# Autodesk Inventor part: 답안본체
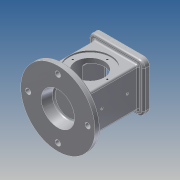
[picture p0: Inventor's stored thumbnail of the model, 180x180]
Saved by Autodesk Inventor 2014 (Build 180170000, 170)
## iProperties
Created: 2018-10
Part Number: 답안본체
Material: 알루미늄 6061
Document SubType Name: Modeling
Designer: net
Density: 2.71 g/cm^3
Appearance: 알루미늄 - 평지
Mass: 988.219 g
Surface Area: 743.902 cm^2
Volume: 364.656 cm^3
Author: net
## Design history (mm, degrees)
sketch "스케치1"
  geometry: C1 r 62.5 at (0, 0); 1 further point
  constraints: 1 centre point, 1 coincident
  dimensions: "d0" = 125 diameter of C1
extrude "돌출1" new body sketch "스케치1" distance "d1" = 10; taper "d2" = 0 deg
sketch "스케치2"
  geometry: L1 (-37, -33)-(37, -33); L2 (37, -33)-(37, 33); L3 (37, 33)-(-37, 33); L4 (-37, 33)-(-37, -33); L5 (-37, -33)-(37, 33); L6 (37, -33)-(-37, 33); C1 r 62.5 at (0, 0) reference
  constraints: 12 end point, 2 midpoint, 2 parallel, 1 horizontal, 1 perpendicular
  dimensions: "d3" = 66 distance of L3.end L1.start; "d4" = 74 distance of L2.end L3.end
extrude "돌출2" join sketch "스케치2" distance "d5" = 98; taper "d6" = 0 deg
sketch "스케치3"
  geometry: L1 (-37, -33)-(37, -33) reference; L2 (37, -33)-(37, 33) reference; L3 (37, 33)-(-37, 33) reference; L4 (-37, 33)-(-37, -33) reference; L5 (-46, -41)-(46, -41); L6 (46, -41)-(46, 41); L7 (46, 41)-(-46, 41); L8 (-46, 41)-(-46, -41); L9 (-46, -41)-(46, 41); L10 (46, -41)-(-46, 41); 1 further point
  constraints: 12 end point, 2 midpoint, 2 parallel, 1 horizontal, 1 perpendicular
  dimensions: "d7" = 92 distance of L6.end L7.end; "d8" = 82 distance of L7.end L5.start
extrude "돌출3" join sketch "스케치3" distance "d9" = 10; taper "d10" = 0 deg
sketch "스케치5"
  geometry: L1 (-26, -26)-(26, -26); L2 (26, -26)-(26, 26); L3 (26, 26)-(-26, 26); L4 (-26, 26)-(-26, -26); L5 (-26, -26)-(26, 26); L6 (26, -26)-(-26, 26); L7 (-22, -22)-(22, -22); L8 (22, -22)-(22, 22); L9 (22, 22)-(-22, 22); L10 (-22, 22)-(-22, -22); L11 (-22, -22)-(22, 22); L12 (22, -22)-(-22, 22); 1 further point
  constraints: 24 end point, 4 midpoint, 4 parallel, 2 horizontal, 2 perpendicular
  dimensions: "d16" = 52 distance of L2.end L3.end; "d17" = 52 distance of L3.end L1.start; "d18" = 44 distance of L8.end L9.end; "d19" = 44 distance of L7.end L8.end
extrude "돌출5" cut sketch "스케치5" distance "d20" = 8; taper "d21" = 0 deg
extrude "돌출6" cut sketch "스케치5" distance "d22" = 82; taper "d23" = 0 deg
sketch "스케치6"
  geometry: L1 (-25.5, -10)-(99.5, -10) reference; L2 (37, -10)-(37, 44); C1 r 35 at (37, 44); C2 r 24 at (37, 44)
  constraints: 2 centre point, 2 coincident, 2 end point, 1 perpendicular
  dimensions: "d24" = 54 distance of L2.start L2.end; "d25" = 70 diameter of C1; "d26" = 48 diameter of C2
extrude "돌출7" cut sketch "스케치6" distance "d27" = 3; taper "d28" = 0 deg
extrude "돌출8" cut sketch "스케치6" distance "d29" = 147.25; taper "d30" = 0 deg
node "작업 평면1"
sketch "스케치8"
  geometry: C1 r 24 at (37, 44) reference; C2 r 35 at (37, 44); 1 further point
  constraints: 1 centre point, 1 coincident
  dimensions: "d31" = 70 diameter of C2
extrude "돌출9" cut sketch "스케치8" distance "d32" = 3; taper "d33" = 0 deg
sketch "스케치9"
  geometry: L1 (-37, -33)-(-37, 33) reference; L2 (-37, 33)-(37, 33) reference; L3 (37, 33)-(37, -33) reference; L4 (37, -33)-(-37, -33) reference; C1 r 62.5 at (0, 0) reference; C2 r 62.5 at (0, 0) reference; C3 r 4.5 at (0, 50); C4 r 4.5 at (50, 0); C5 r 4.5 at (0, -50); C6 r 4.5 at (-50, 0); A1 r 50 centre (0, 0) between (0, 50) and (50, 0)
  constraints: 5 centre point, 4 point on circle, 2 horizontal alignment, 2 vertical alignment, 1 coincident
  dimensions: "d34" = 100 diameter of A1; "d35" = 9 diameter of C3; "d36" = 9 diameter of C4; "d37" = 9 diameter of C5; "d38" = 9 diameter of C6
extrude "돌출10" cut sketch "스케치9" distance "d39" = 19.75; taper "d40" = 0 deg
sketch "스케치10"
  geometry: L1 (-36, -31)-(36, -31); L2 (36, -31)-(36, 31); L3 (36, 31)-(-36, 31); L4 (-36, 31)-(-36, -31); L5 (-36, -31)-(36, 31); L6 (36, -31)-(-36, 31); 5 further points
  constraints: 12 end point, 4 coincident, 2 midpoint, 2 parallel, 1 horizontal, 1 perpendicular
  dimensions: "d41" = 72 distance of L2.end L3.end; "d42" = 62 distance of L1.end L2.end
hole "구멍1" sketch "스케치10" at (-36, 31), (36, 31), (36, -31), (-36, -31) diameter "d43" = 3.242; stored, may be unused: countersink angle "d47" = 90 deg, drill point angle "d49" = 118 deg; dims "d44" = 4, "d45" = 4, "d46" = 2, "d48" = 6
sketch "스케치11" dims "d50" = 58
  geometry: C1 r 24 at (0, 0) reference; C2 r 35 at (0, 0) reference; 3 further points
  constraints: 2 vertical alignment, 1 coincident, 2 other
hole "구멍2" sketch "스케치11" at (0, 29) diameter "d51" = 3.242; stored, may be unused: countersink angle "d55" = 90 deg, drill point angle "d57" = 118 deg; dims "d52" = 4, "d53" = 4, "d54" = 2, "d56" = 6
node "작업 평면2"
sketch "스케치12"
  geometry: L1 (-29.5, -10)-(95.5, -10) reference; L2 (33, -10)-(33, 27); L3 (33, 27)-(33, 70); 2 further points
  constraints: 4 end point, 2 coincident, 1 collinear, 1 perpendicular
  dimensions: "d61" = 37 distance of L2.start L2.end; "d62" = 43 distance of L2.end L3.end
hole "구멍3" sketch "스케치12" at (33, 70), (33, 27) diameter "d63" = 4.134; stored, may be unused: countersink angle "d67" = 90 deg, drill point angle "d69" = 118 deg; dims "d64" = 4, "d65" = 4, "d66" = 2, "d68" = 32.75
sketch "스케치13"
  geometry: 4 further points
  constraints: 1 other
  dimensions: "d70" = 46 horizontal distance of point (46, -4) point (0, 0); "d71" = 4 vertical distance of point (92, 0) point (46, -4)
sketch "스케치14"
  geometry: C1 r 62.5 at (0, 0) reference; C2 r 28 at (0, 0)
  constraints: 1 centre point, 1 coincident
  dimensions: "d72" = 56 diameter of C2
extrude "돌출11" cut sketch "스케치14" distance "d73" = 18; taper "d74" = -10 deg
fillet "모깎기1" dims "d75" = 10
chamfer "모따기1" distance "d76" = 1; stored, may be unused: second distance "d77" = 2, angle "d78" = 45 deg
fillet "모깎기2" dims "d79" = 3
fillet "모깎기3" dims "d80" = 3
fillet "모깎기4" dims "d81" = 3
fillet "모깎기5" dims "d82" = 3
fillet "모깎기6" dims "d83" = 3
fillet "모깎기7" dims "d84" = 3
fillet "모깎기8" dims "d85" = 3
feature "엠보싱1" dims "d86" = 0.5, "d87" = 0
node "솔리드1"
pattern_circular "원형 패턴1" dims angle "d59" = 360 deg
mirror "대칭1"
node "투영된 루프1"
